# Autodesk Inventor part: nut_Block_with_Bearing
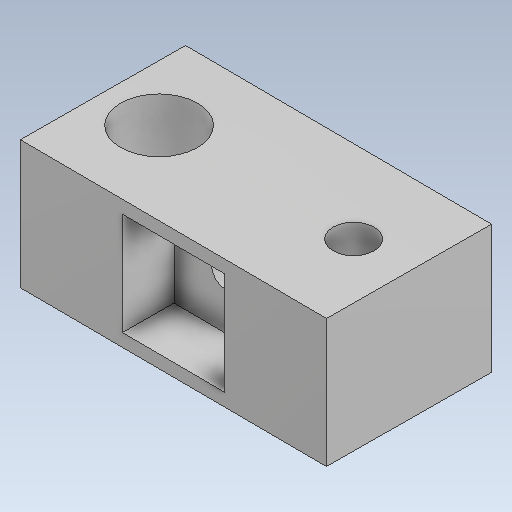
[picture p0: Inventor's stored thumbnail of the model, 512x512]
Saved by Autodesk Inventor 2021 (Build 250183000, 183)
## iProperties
Created: 2026-10
Part Number: nut_Block_with_Bearing
Material: Steel
Document SubType Name: Modeling
Designer: hp
Density: 7.85 g/cm^3
Appearance: Default
Author: hp
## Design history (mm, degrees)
feature "Body1"
body "Solid1"
